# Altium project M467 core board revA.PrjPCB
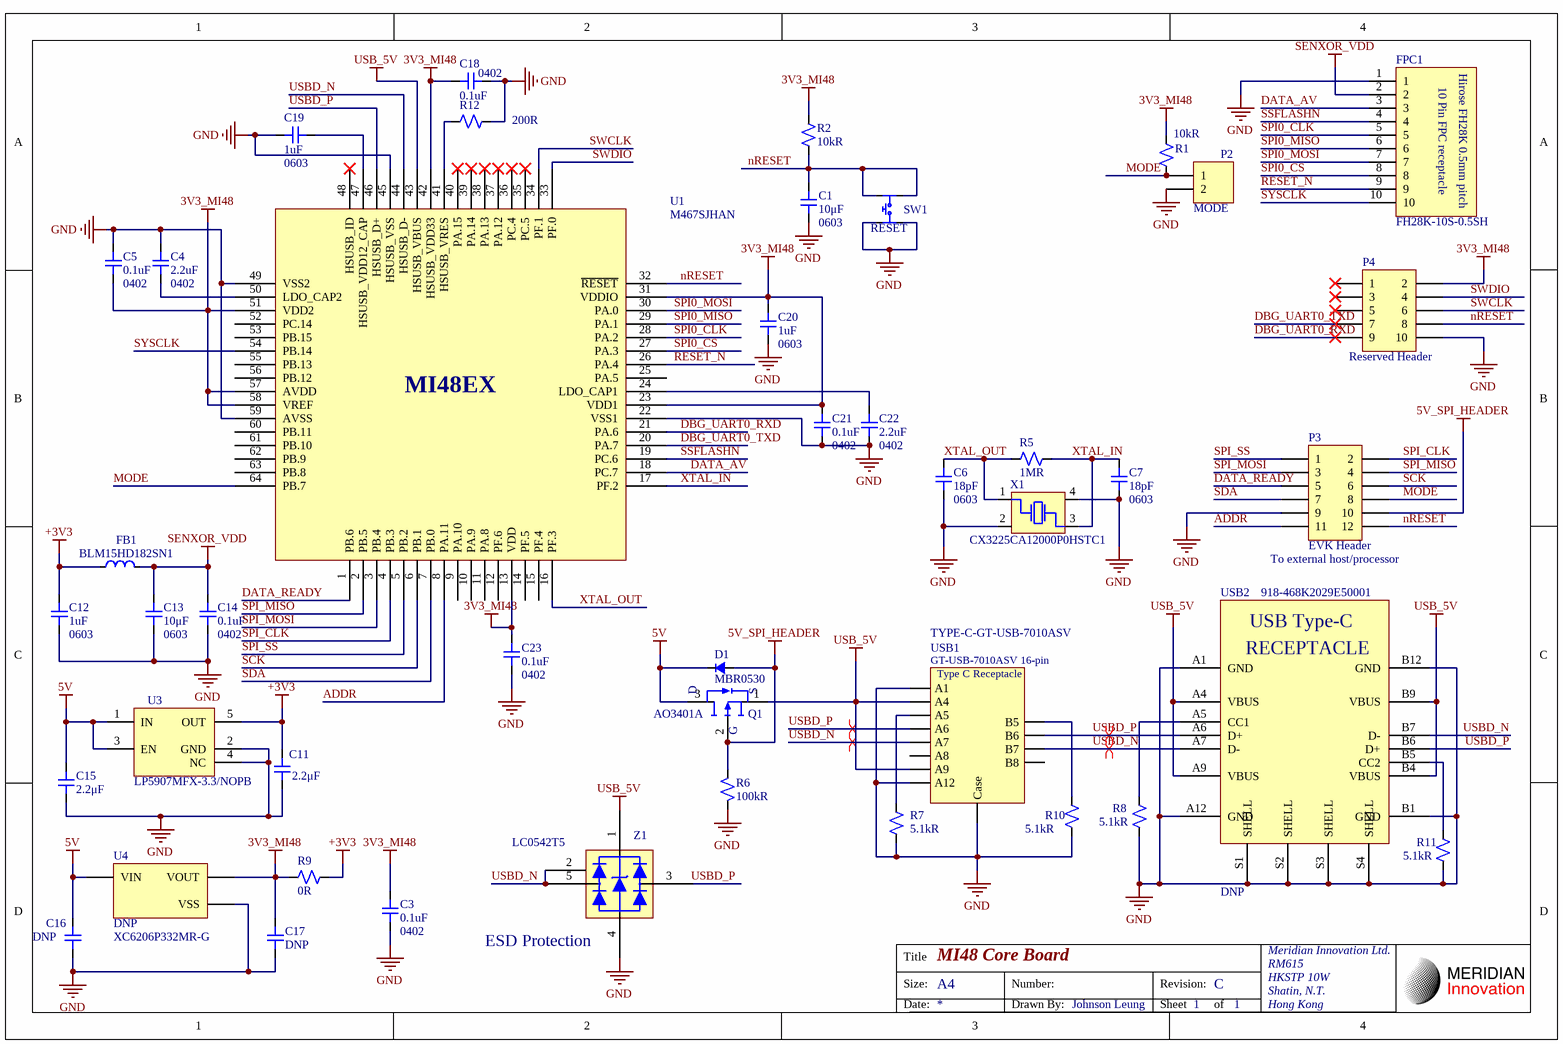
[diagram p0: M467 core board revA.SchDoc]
1 sheet, 44 parts. Net scope: global (net labels, ports and power ports of the same name join across sheets).
Board file: M467 core board revA.PcbDoc

## Sheet M467 core board revA.SchDoc: MI48 Core Board
size A4; Engineer: Johnson Leung; Organization: Meridian Innovation Ltd.; Address1: RM615; Address2: HKSTP 10W; Address3: Shatin, N.T.; Address4: Hong Kong; Revision: C; SheetNumber: 1; SheetTotal: 1

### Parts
C1  10μF  Package (Imperial): 0603  [XCAM-C0603]
C3  0.1uF  Package (Imperial): 0402  [XCAM-C0402]
C4  2.2uF  Package (Imperial): 0402  [XCAM-C0402]
C5  0.1uF  Package (Imperial): 0402  [XCAM-C0402]
C6  18pF  Package (Imperial): 0603  [XCAM-C0603]
C7  18pF  Package (Imperial): 0603  [XCAM-C0603]
C11  2.2μF  [XCAM-C0603]
C12  1uF  Package (Imperial): 0603  [XCAM-C0603]
C13  10μF  Package (Imperial): 0603  [XCAM-C0603]
C14  0.1uF  Package (Imperial): 0402  [XCAM-C0402]
C15  2.2μF  [XCAM-C0603]
C16  DNP  [XCAM-C0603]
C17  DNP  [XCAM-C0603]
C18  0.1uF  Package (Imperial): 0402  [XCAM-C0402]
C19  1uF  Package (Imperial): 0603  [XCAM-C0603]
C20  1uF  Package (Imperial): 0603  [XCAM-C0603]
C21  0.1uF  Package (Imperial): 0402  [XCAM-C0402]
C22  2.2uF  Package (Imperial): 0402  [XCAM-C0402]
C23  0.1uF  Package (Imperial): 0402  [XCAM-C0402]
D1  MBR0530  [SOD123]
FB1  BLM15HD182SN1  [XCAM-R0402]
FPC1  FH28K-10S-0.5SH  [FH28K-10S-0.5SH-WITH-PANTHER]
P2  MODE  [HDR1X2]
P3  EVK Header  [HDR2X6]
P4  Reserved Header  [HDR2X5]
Q1  AO3401A  [SOT23]
R1  10kR  [XCAM-R0402]
R2  10kR  [XCAM-R0402]
R5  1MR  [XCAM-R0402]
R6  100kR  [XCAM-R0402]
R7  5.1kR  [XCAM-R0402]
R8  5.1kR  [XCAM-R0402]
R9  0R  [R0805]
R10  5.1kR  [XCAM-R0402]
R11  5.1kR  [XCAM-R0402]
R12  200R  [XCAM-R0402]
SW1  SKRPABE010  [SKRP Series]  (value not drawn)
U1  M467SJHAN  [TSQFP40P900X900X160-64N]
U3  LP5907MFX-3.3/NOPB  [LP5907 SOT-23]
U4  DNP  [SOT23]
USB1  TYPE-C-GT-USB-7010ASV  [GT-USB-7010ASV]
USB2  DNP  [918-468K2029E50001]
X1  CX3225CA12000P0HSTC1  [CX3225CA]
Z1  LC0542T5  [SOT553-TI]

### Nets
3V3_MI48: C3.1 C5.2 C17.2 C18.1 C20.1 C21.1 C23.1 P4.2 R1.2 R2.2 R9.1 U1.13(VDD) U1.23(VDD1) U1.31(VDDIO) U1.42(HSUSB_VDD33) U1.51(VDD2) U1.57(AVDD) U1.58(VREF) U4.1(VOUT)
5V: C15.2 C16.2 D1.1 Q1.3(D) U3.1(IN) U3.3(EN) U4.3(VIN)
5V_SPI_HEADER: D1.2 P3.10 Q1.2(G) R6.2
+3V3: C11.2 C12.1 FB1.1 R9.2 U3.5(OUT)
GND: C1.2 C3.2 C4.1 C5.1 C6.2 C7.2 C11.1 C12.2 C13.2 C14.2 C15.1 C16.1 C17.1 C18.2 C19.1 C20.2 C21.2 C22.2 C23.2 FPC1.1 P2.2 P3.9 P4.10 R6.1 R7.2 R8.2 R10.2 R11.2 R12.2 SW1.3 SW1.4 U1.22(VSS1) U1.45(HSUSB_VSS) U1.49(VSS2) U1.59(AVSS) U3.2(GND) U3.4(NC) U4.2(VSS) USB1.A1 USB1.A12 USB1.E(Case) USB2.A1(GND) USB2.A12(GND) USB2.B1(GND) USB2.B12(GND) USB2.S1(SHELL) USB2.S2(SHELL) USB2.S3(SHELL) USB2.S4(SHELL) X1.2 X1.4 Z1.4(GND)
SENXOR_VDD: C13.1 C14.1 FB1.2 FPC1.2
USB_5V: Q1.1(S) U1.43(HSUSB_VBUS) USB1.A4 USB1.A9 USB2.A4(VBUS) USB2.A9(VBUS) USB2.B4(VBUS) USB2.B9(VBUS) Z1.1(Vcc)
ADDR: P3.11 U1.8(PA.11)
DATA_AV: FPC1.3 U1.18(PC.7)
DATA_READY: P3.5 U1.1(PB.6)
DBG_UART0_RXD: P4.9 U1.21(PA.6)
DBG_UART0_TXD: P4.7 U1.20(PA.7)
MODE: P2.1 P3.8 R1.1 U1.64(PB.7)
nRESET: C1.1 P3.12 P4.8 R2.1 SW1.1 SW1.2 U1.32(~{RESET})
RESET_N: FPC1.9 U1.26(PA.4)
SCK: P3.6 U1.6(PB.1)
SDA: P3.7 U1.7(PB.0)
SPI0_CLK: FPC1.5 U1.28(PA.2)
SPI0_CS: FPC1.8 U1.27(PA.3)
SPI0_MISO: FPC1.6 U1.29(PA.1)
SPI0_MOSI: FPC1.7 U1.30(PA.0)
SPI_CLK: P3.2 U1.4(PB.3)
SPI_MISO: P3.4 U1.2(PB.5)
SPI_MOSI: P3.3 U1.3(PB.4)
SPI_SS: P3.1 U1.5(PB.2)
SSFLASHN: FPC1.4 U1.19(PC.6)
SWCLK: P4.6 U1.34(PF.1)
SWDIO: P4.4 U1.33(PF.0)
SYSCLK: FPC1.10 U1.54(PB.14)
USBD_N: U1.44(HSUSB_D-) USB1.A7 USB1.B7 USB2.A7(D-) USB2.B7(D-) Z1.2(NC) Z1.5(IO2)
USBD_P: U1.46(HSUSB_D+) USB1.A6 USB1.B6 USB2.A6(D+) USB2.B6(D+) Z1.3(IO1)
XTAL_IN: C7.1 R5.1 U1.17(PF.2) X1.3
XTAL_OUT: C6.1 R5.2 U1.16(PF.3) X1.1
NetC4_2: C4.2 U1.50(LDO_CAP2)
NetC19_2: C19.2 U1.47(HSUSB_VDD12_CAP)
NetC22_1: C22.1 U1.24(LDO_CAP1)
NetR7_1: R7.1 USB1.A5
NetR8_1: R8.1 USB2.A5(CC1)
NetR10_1: R10.1 USB1.B5
NetR11_1: R11.1 USB2.B5(CC2)
NetR12_1: R12.1 U1.41(HSUSB_VRES)

Not connected (* = marked no-connect by the designer): P4 1* 3* 5*; U1 9(PA.10) 10(PA.9) 11(PA.8) 12(PF.6) 14(PF.5) 15(PF.4) 25(PA.5) 35(PC.5)* 36(PC.4)* 37(PA.12)* 38(PA.13)* 39(PA.14)* 40(PA.15)* 48(HSUSB_ID)* 52(PC.14) 53(PB.15) 55(PB.13) 56(PB.12) 60(PB.11) 61(PB.10) 62(PB.9) 63(PB.8); USB1 A8 B8

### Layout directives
differential pair: USBD_N, USBD_P

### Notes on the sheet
- (near SW1) RESET
- (near P3) To external host/processor
- 918-468K2029E50001
- XC6206P332MR-G
- (near Z1) ESD Protection

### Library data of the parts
C1 C12 C13 C19 C20 = Capacitor SMD: Vendor: TBD; Voltage Rating: 6.3V; Tolerance: 20%; Dielectric: X5R
C3-C5 C14 C18 C21-C23 = Capacitor SMD: Vendor: TBD; Voltage Rating: 6.3V; Tolerance: 10%; Dielectric: X5R
C6 C7 = Capacitor SMD: Vendor: TBD; Voltage Rating: 50V; Tolerance: 1%; Dielectric: C0G
C11 C15 = Capacitor SMD: Vendor: TBD; Dielectric: X5R; Voltage Rating: 10V; Tolerance: 20%
C16 C17 = Capacitor SMD: Vendor: TBD; Voltage Rating: 6.3V; Dielectric: X5R; Tolerance: 20%
D1 = MBR0530: Surface Mount Schottky Power Rectifier
FB1 = Inductor SMD: Manufacturer: TBD
FPC1 = FH28K-10S-0.5SH: Hirose 0.5 mm Pitch, FPC Receptacle, 10P; Manufacturer #: FH26-15S-0.3SHW(60)
P2 = Header 2: Header, 2-Pin
P3 = Header 6X2: Header, 6-Pin, Dual row
P4 = Header 5X2: Header, 5-Pin, Dual row
Q1 = AO3401A: 30V 4.0A P-Channel MOSFET
R1 R2 R5-R8 R10 R11 = Resistor SMD: Manufacturer: TBD; Tolerance: 5%
R9 = Resistor SMD: Manufacturer: TBD
R12 = Resistor SMD: Manufacturer: TBD; Tolerance: 1%
SW1 = TACT-SW-4P: 4-pin Tactile Switch
U1 = M467SJHAN: Nuvoton M467SJHAN
U3 = LP5907MFX-X.X/NOPB: LP5907 250-mA, Ultra-Low-Noise LDO, SOT23-5 Package
U4 = XC6206: Torex Positive Voltage LDO
USB1 = TYPE-C-GT-USB-7010ASV: 5A 1 Surface Mount 16 Female -45℃~+85℃ Type-C SMD USB Connectors ROHS
USB2 = USB Type-C Receptacle Straight 1: Jing Extension of the Electronic Co. 918-468K2029E50001
X1 = XTAL-4P: Passive 4-pin Oscillator
Z1 = TPD2E001DRLR: Leiditech TVS Diode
